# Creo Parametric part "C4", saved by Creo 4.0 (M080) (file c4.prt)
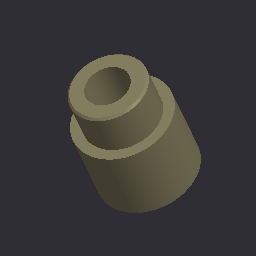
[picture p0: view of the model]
Units: Inch lbm Second (Pro/E Default); INCH, POUND, SECS

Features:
  1. datum plane "DTM1"
  2. datum plane "DTM2"
  3. datum plane "DTM3"
  4. protrusion
  5. hole
  6. chamfer

Layers: BASE_DAT

Surfaces: 5 cylinder, 3 plane, 2 cone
